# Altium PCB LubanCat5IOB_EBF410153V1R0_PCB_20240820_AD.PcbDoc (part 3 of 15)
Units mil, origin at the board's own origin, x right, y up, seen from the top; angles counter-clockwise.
Board outline 6811.02 x 4055.12 mil, 6 copper layers (TOP, GND02, ART03, ART04, PWR05, BOTTOM), stack 59.279 mil thick; 981 components, 783 nets, 3627 pads, 2669 vias.
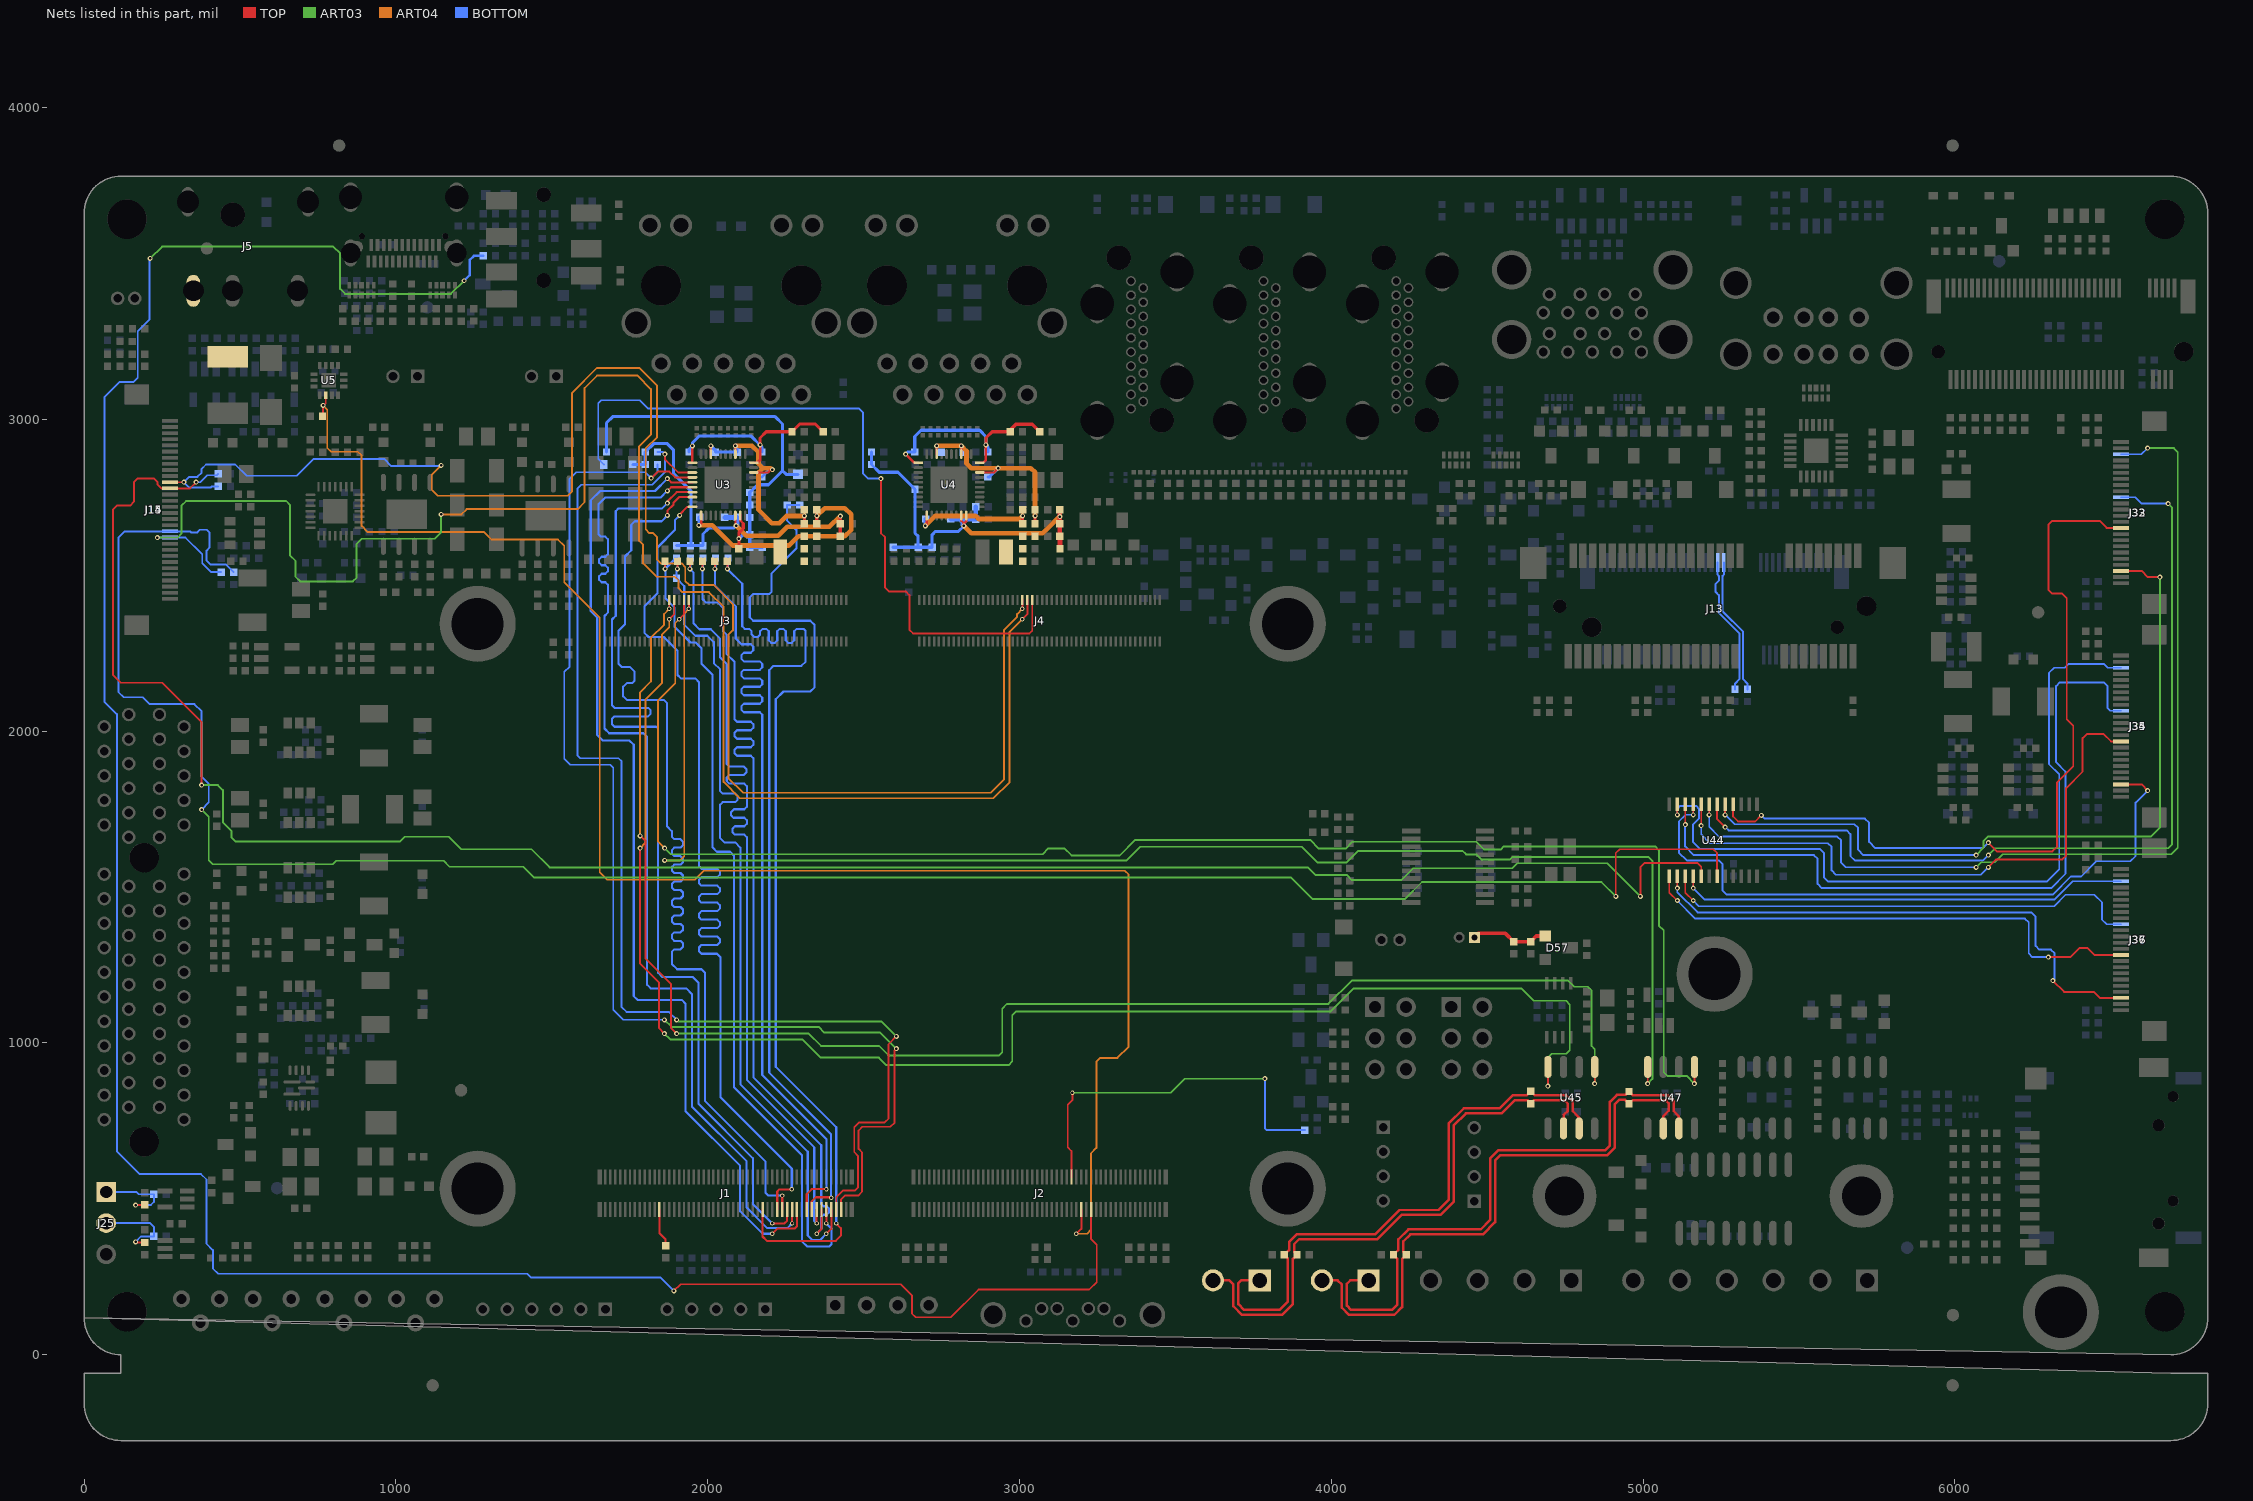
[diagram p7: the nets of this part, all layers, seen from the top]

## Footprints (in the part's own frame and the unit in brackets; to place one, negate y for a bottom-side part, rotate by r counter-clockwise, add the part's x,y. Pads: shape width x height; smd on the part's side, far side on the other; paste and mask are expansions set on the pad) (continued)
MARK#15 [mil] "MARK"
  round 40 smd far side: 1(-5748,-41) 1(-5323.89,-370.95) 1(-5023.89,3605.43) 1(-4933,2659) 1(-149.09,-370.95) 1(-149.09,3605.43) 1(-148,3380) 1(125,1126)
  round 40 smd: 1(-5523,2973) 1(-5041,148) 1(-295,3164) 1(0,0)
  body extent -5563,-411 40,3645, height 150
MARK#16 [mil] "MARK"
  round 40 smd far side: 1(-5453,-3205) 1(-5028.89,-3534.95) 1(-4728.89,441.43) 1(-4638,-505) 1(145.91,-3534.95) 1(145.91,441.43) 1(147,216) 1(420,-2038)
  round 40 smd: 1(-5228,-191) 1(-4746,-3016) 1(0,0) 1(295,-3164)
  body extent -5268,-3575 335,481, height 150
MIC2-4R00-TM [mm] "MIC2-4R00-TM"
  round 1.1 / inner round 1.524 / far side round 1.1 hole 0.7: 1(-0.7,-0.55) 2(0.7,-0.55)
  silkscreen extent -2,-2 2,2, body extent -2.11,-2.11 2.11,2.11, height 3.81
MSOP-8 [mm] "MSOP-8"
  rect 0.3x1 smd: 1(-0.975,-2.2) 2(-0.325,-2.2) 3(0.325,-2.2) 4(0.975,-2.2) 5(0.975,2.2) 6(0.325,2.2) 7(-0.325,2.2) 8(-0.975,2.2)
  silkscreen extent -1.5,-3.3 1.5,1.5, body extent -1.5,-2.8 1.5,2.8, height 3.81
NANO_SIM [mm] "NANO_SIM"
  rect 0.5x1.3 smd: 1(0.25,6.94) 2(-2.29,6.94) 3(-4.83,6.94) 4(2.47,6.94) 5(1.52,6.94) 6(-1.02,6.94) 7(-3.56,6.94)
  rect 1x2.1 smd: 8(-6.5,5.46) 9(6.5,5.46) 10(-6.5,-6.54) 11(6.5,-6.54)
  round 0.9 hole 0.9 unplated: ""(-5,-5.29) ""(3.5,-5.29)
  silkscreen extent -6.14,-7.6 6.14,5.9, body extent -7.05,-7.64 7.05,7.64, height 3.81
NPTH_M3 [mm] "NPTH_M3"
  round 3.2 / inner round 1.524 / far side round 3.2 hole 3.2 unplated: 1(0,0)
  body extent -3.11,-3.11 3.11,3.11, height 3.81
PCIE_52P [mm] "PCIE_52P"
  rect 0.6x2 smd: 1(-11.8,-4.1) 2(-11.4,4.1) 3(-11,-4.1) 4(-10.6,4.1) 5(-10.2,-4.1) 6(-9.8,4.1) 7(-9.4,-4.1) 8(-9,4.1) 9(-8.6,-4.1) 10(-8.2,4.1) 11(-7.8,-4.1) 12(-7.4,4.1) 13(-7,-4.1) 14(-6.6,4.1) 15(-6.2,-4.1) 16(-5.8,4.1) 17(-2.2,-4.1) 18(-1.8,4.1) 19(-1.4,-4.1) 20(-1,4.1) 21(-0.6,-4.1) 22(-0.2,4.1) 23(0.2,-4.1) 24(0.6,4.1) 25(1,-4.1) 26(1.4,4.1) 27(1.8,-4.1) 28(2.2,4.1) 29(2.6,-4.1) 30(3,4.1) 31(3.4,-4.1) 32(3.8,4.1) 33(4.2,-4.1) 34(4.6,4.1) 35(5,-4.1) 36(5.4,4.1) 37(5.8,-4.1) 38(6.2,4.1) 39(6.6,-4.1) 40(7,4.1) 41(7.4,-4.1) 42(7.8,4.1) 43(8.2,-4.1) 44(8.6,4.1) 45(9,-4.1) 46(9.4,4.1) 47(9.8,-4.1) 48(10.2,4.1) 49(10.6,-4.1) 50(11,4.1) 51(11.4,-4.1) 52(11.8,4.1)
  rect 2.15x2.6 smd: 53(14.65,-3.5) 54(-14.65,-3.5)
  round 1.6 hole 1.6 unplated: ""(-12.5,0)
  round 1.1 hole 1.1 unplated: ""(12.5,0)
  silkscreen extent -13.7,-4.6 13.7,49.64, body extent -15.8,-5.2 15.8,5.2, height 3.81
PCIE_64PIN_1R00 [mm] "PCIE_64PIN_1R00"
  round 1.1 hole 0.7: A1(-16.765,1.25) A4(-13.765,3.25) A12(-3.765,3.25) A15(-0.765,1.25) A18(2.235,3.25) A20(4.235,3.25) A23(7.235,1.25) A24(8.235,3.25) A27(11.235,1.25) A28(12.235,3.25) A31(15.235,1.25) B4(-13.765,-3.25) B7(-10.765,-1.25) B13(-2.765,-1.25) B16(0.235,-3.25) B18(2.235,-3.25) B21(5.235,-1.25) B22(6.235,-3.25) B25(9.235,-1.25) B26(10.235,-3.25) B29(13.235,-1.25) B32(16.235,-3.25)
  round 1.1 / inner round 1.524 / far side round 1.1 hole 0.7: A2(-15.765,3.25) A3(-14.765,1.25) A5(-12.765,1.25) A6(-11.765,3.25) A7(-10.765,1.25) A8(-9.765,3.25) A9(-8.765,1.25) A10(-7.765,3.25) A11(-6.765,1.25) A13(-2.765,1.25) A14(-1.765,3.25) A16(0.235,3.25) A17(1.235,1.25) A19(3.235,1.25) A21(5.235,1.25) A22(6.235,3.25) A25(9.235,1.25) A26(10.235,3.25) A29(13.235,1.25) A30(14.235,3.25) A32(16.235,3.25) B1(-16.765,-1.25) B2(-15.765,-3.25) B3(-14.765,-1.25) B5(-12.765,-1.25) B6(-11.765,-3.25) B8(-9.765,-3.25) B9(-8.765,-1.25) B10(-7.765,-3.25) B11(-6.765,-1.25) B12(-3.765,-3.25) B14(-1.765,-3.25) B15(-0.765,-1.25) B17(1.235,-1.25) B19(3.235,-1.25) B20(4.235,-3.25) B23(7.235,-1.25) B24(8.235,-3.25) B27(11.235,-1.25) B28(12.235,-3.25) B30(14.235,-3.25) B31(15.235,-1.25)
  round 2.4 hole 2.4 unplated: ""(-5.115,0) ""(18.035,0)
  silkscreen extent -19.61,-4.39 19.61,4.39, body extent -19.61,-4.39 19.61,4.39, height 3.81
PH-1X2-2P0_L [mm] "PH-1X2-2P0_L"
  rect 1.1x1.1 / inner round 1.524 / far side rect 1.1x1.1 hole 0.7: 1(-1,-0.6)
  round 1.1 / inner round 1.524 / far side round 1.1 hole 0.7: 2(1,-0.6)
  silkscreen extent -3,-2.6 3,2.6, body extent -3.1,-2.7 3.1,2.7, height 3.81
PH-1X4-2P0 [mm] "PH-1X4-2P0"
  rect 1.1x1.1 / inner round 1.524 / far side rect 1.1x1.1 hole 0.7: 1(-3,-0.6)
  round 1.1 / inner round 1.524 / far side round 1.1 hole 0.7: 2(-1,-0.6) 3(1,-0.6)
  round 1.1 hole 0.7: 4(3,-0.6)
  silkscreen extent -5,-2.6 5,2.6, body extent -5.1,-2.7 5.1,2.7, height 3.81
PH-1X5-2P0 [mm] "PH-1X5-2P0"
  rect 1.1x1.1 / inner round 1.524 / far side rect 1.1x1.1 hole 0.7: 1(-4,-0.6)
  round 1.1 / inner round 1.524 / far side round 1.1 hole 0.7: 2(-2,-0.6) 3(0,-0.6) 4(2,-0.6)
  round 1.1 hole 0.7: 5(4,-0.6)
  silkscreen extent -6,-2.6 6,2.6, body extent -6.13,-2.73 6.13,2.73, height 3.81
PH-1X6-2P0 [mm] "PH-1X6-2P0"
  rect 1.1x1.1 / inner round 1.524 / far side rect 1.1x1.1 hole 0.7: 1(-5,-0.6)
  round 1.1 hole 0.7: 2(-3,-0.6) 4(1,-0.6) 6(5,-0.6)
  round 1.1 / inner round 1.524 / far side round 1.1 hole 0.7: 3(-1,-0.6) 5(3,-0.6)
  silkscreen extent -7,-2.6 7,2.6, body extent -7.1,-2.7 7.1,2.7, height 3.81
QFN12-2R00X3R00 [mm] "QFN12-2R00X3R00"
  oval 1.4x0.25 smd: 1(-0.6,0.5) 2(-0.6,-0.5) 7(0.6,0)
  oval 0.25x0.8 smd: 3(-0.75,-1.45) 4(-0.25,-1.45) 5(0.25,-1.45) 6(0.75,-1.45) 9(0.75,1.45) 10(0.25,1.45) 11(-0.25,1.45) 12(-0.75,1.45)
  oval 0.8x0.25 smd: 8(0.9,0.5)
  silkscreen extent -2.25,-2 1.5,2, body extent -1.5,-2 1.5,2, height 3.81
QFN24 [mm] "QFN24"
  rect 1x0.3 smd: 1(-2.1,1.25) 2(-2.1,0.75) 3(-2.1,0.25) 4(-2.1,-0.25) 5(-2.1,-0.75) 6(-2.1,-1.25) 13(2.1,-1.25) 14(2.1,-0.75) 15(2.1,-0.25) 16(2.1,0.25) 17(2.1,0.75) 18(2.1,1.25)
  rect 0.3x1 smd: 7(-1.25,-2.1) 8(-0.75,-2.1) 9(-0.25,-2.1) 10(0.25,-2.1) 11(0.75,-2.1) 12(1.25,-2.1) 19(1.25,2.1) 20(0.75,2.1) 21(0.25,2.1) 22(-0.25,2.1) 23(-0.75,2.1) 24(-1.25,2.1)
  rect 2x2 smd: 25(0,0)
  silkscreen extent -3.35,-2.1 2.1,2.1, body extent -2.7,-2.7 2.7,2.7, height 3.81
QFN28_0R45-4X4EP2R6X2R6 [mm] "QFN28_0R45-4X4EP2R6X2R6"
  oval 0.8x0.2 smd: 1(-2,1.35)
  rect 0.8x0.2 smd: 2(-2,0.9) 3(-2,0.45) 4(-2,0) 5(-2,-0.45) 6(-2,-0.9) 7(-2,-1.35) 15(2,-1.35) 16(2,-0.9) 17(2,-0.45) 18(2,0) 19(2,0.45) 20(2,0.9) 21(2,1.35)
  rect 0.2x0.8 smd: 8(-1.35,-2) 9(-0.9,-2) 10(-0.45,-2) 11(0,-2) 12(0.45,-2) 13(0.9,-2) 14(1.35,-2) 22(1.35,2) 23(0.9,2) 24(0.45,2) 25(0,2) 26(-0.45,2) 27(-0.9,2) 28(-1.35,2)
  rect 2x2 smd: 29(0,0)
  silkscreen extent -3.15,-2 2,2.03, body extent -2.5,-2.5 2.5,2.5, height 3.81
QFP_40P_R [mil] "QFP_40P_R"
  oval 31.5x8.66 smd: 1(-98.43,70.87) 2(-98.43,55.12) 3(-98.43,39.37) 4(-98.43,23.62) 5(-98.43,7.87) 6(-98.43,-7.87) 7(-98.43,-23.62) 8(-98.43,-39.37) 9(-98.43,-55.12) 10(-98.43,-70.87) 21(98.43,-70.87) 22(98.43,-55.12) 23(98.43,-39.37) 24(98.43,-23.62) 25(98.43,-7.87) 26(98.43,7.87) 27(98.43,23.62) 28(98.43,39.37) 29(98.43,55.12) 30(98.43,70.87)
  oval 8.66x31.5 smd: 11(-70.87,-98.43) 12(-55.12,-98.43) 13(-39.37,-98.43) 14(-23.62,-98.43) 15(-7.87,-98.43) 16(7.87,-98.43) 17(23.62,-98.43) 18(39.37,-98.43) 19(55.12,-98.43) 20(70.87,-98.43) 31(70.87,98.43) 32(55.12,98.43) 33(39.37,98.43) 34(23.62,98.43) 35(7.87,98.43) 36(-7.87,98.43) 37(-23.62,98.43) 38(-39.37,98.43) 39(-55.12,98.43) 40(-70.87,98.43)
  rect 118.11x118.11 smd: 41(0,0)
  silkscreen extent -124,-98 98,124, body extent -116,-116 116,116, height 150
R0201#1 [mm] "R0201"
  rect 0.35x0.35 smd: 1(-0.275,0) 2(0.275,0)
  silkscreen extent -0.51,-0.25 0.51,0.25
R0201#2 [mm] "R0201"
  rect 0.35x0.35 smd: 1(0.275,0) 2(-0.275,0)
  silkscreen extent -0.51,-0.25 0.51,0.25, body extent -0.47,-0.18 0.47,0.18, height 3.81
R0402#1 [mil] "R0402"
  rect 23.6x23.6 smd: 1(-19.68,0) 2(19.68,0)
  silkscreen extent -37,-17 37,17, body extent -37,-17 37,17, height 150
R0402#2 [mil] "R0402"
  rect 23.6x23.6 smd: 1(19.68,0) 2(-19.68,0)
  silkscreen extent -37,-17 37,17, body extent -37,-17 37,17, height 150
R0603#1 [mil] "R0603"
  rect 31.5x31.5 smd: 1(-31.5,0) 2(31.5,0)
  silkscreen extent -54,-24 55,24, body extent -47,-16 47,16, height 150
R0603#2 [mil] "R0603"
  rect 31.5x31.5 smd: 1(31.5,0) 2(-31.5,0)
  silkscreen extent -55,-24 54,24, body extent -47,-16 47,16, height 150
R0805#1 [mil] "R0805"
  rect 40x45 smd: 1(-40,0) 2(40,0)
  silkscreen extent -70,-35 70,35, body extent -60,-25 60,25, height 150
R0805#2 [mil] "R0805"
  rect 40x45 smd: 1(40,0) 2(-40,0)
  silkscreen extent -70,-35 70,35, body extent -60,-25 60,25, height 150
SMA_CA [mm] "SMA_CA"
  rect 2.1x1.8 smd: 1(-2.2,0) 2(2.2,0)
  silkscreen extent -2.2,-1.3 2.2,1.3, body extent -3.3,-1.4 3.3,1.4, height 3.81
SMD4-6R80X2R50 [mm] "SMD4-6R80X2R50"
  rect 0.8x1.2 smd: 1(1.905,-1) 2(0.635,-1) 3(-0.635,-1) 4(-1.905,-1)
  silkscreen extent -3.4,-2.24 3.4,1.71, body extent -3.6,-1.8 3.6,1.8, height 3.81
SMTSO-M2R5 [mm] "SMTSO-M2R5"
  round 6.2 / inner round 5.2 / far side round 5.2 hole 4.22: 1(0,0)
  body extent -3.21,-3.21 3.21,3.21, height 3.81
SMTSO-M3#1 [mm] "SMTSO-M3"
  round 6.2 / inner round 5.2 / far side round 5.2 hole 4.22: 1(0,0)
  body extent -3.21,-3.21 3.21,3.21, height 3.81
SMTSO-M3#2 [mm] "SMTSO-M3"
  round 5.2 / inner round 5.2 / far side round 6.2 hole 4.22: 1(0,0)
  body extent -3.21,-3.21 3.21,3.21, height 3.81
SOD523 [mm] "SOD523"
  rect 0.6x0.7 smd: 1(-0.71,0) 2(0.71,0)
  silkscreen extent -1.3,-0.5 0.6,0.5, body extent -1.1,-0.4 1.1,0.4, height 3.81
SOD-123#1 [mm] "SOD-123"
  rect 1.2x1.4 smd: 1(1.7,0) 2(-1.7,0)
  silkscreen extent -1.8,-0.9 1.8,0.9, body extent -2.4,-1 2.4,1, height 3.81
SOD-123#2 [mm] "SOD-123"
  rect 1.2x1.4 smd: 1(-1.7,0) 2(1.7,0)
  silkscreen extent -1.8,-0.9 1.8,0.9, body extent -2.4,-1 2.4,1, height 3.81
SOIC16 [mil] "SOIC16"
  oval 80x24 smd: 1(-109.8,174.8) 2(-109.8,125.2) 3(-109.8,74.8) 4(-109.8,25.2) 5(-109.8,-25.2) 6(-109.8,-74.8) 7(-109.8,-125.2) 8(-109.8,-174.8) 9(109.8,-174.8) 10(109.8,-125.2) 11(109.8,-74.8) 12(109.8,-25.2) 13(109.8,25.2) 14(109.8,74.8) 15(109.8,125.2) 16(109.8,174.8)
  silkscreen extent -179,-197 59,197, body extent -157,-205 157,205, height 150
SOP8 [mm] "SOP8"
  oval 0.6x1.8 smd: 1(-1.905,-2.5) 2(-0.635,-2.5) 3(0.635,-2.5) 4(1.905,-2.5) 5(1.905,2.5) 6(0.635,2.5) 7(-0.635,2.5) 8(-1.905,2.5)
  silkscreen extent -2.5,-4.15 2.5,1.4, body extent -2.5,-3.5 2.5,3.5, height 3.81
SOP-8-EP-2R5X3R4 [mm] "SOP-8-EP-2R5X3R4"
  oval 0.4x1.4 smd: 1(-1.905,-2.6) 2(-0.635,-2.6) 3(0.635,-2.6) 4(1.905,-2.6) 5(1.905,2.6) 6(0.635,2.6) 7(-0.635,2.6) 8(-1.905,2.6)
  rect 3.3x2.4 smd: 9(0,0)
  silkscreen extent -2.79,-3.18 2.5,2, body extent -2.5,-3 2.5,3, height 3.81
SOT23#1 [mil] "SOT23"
  rect 36x36 smd: 1(-37.5,-43.5) 2(37.5,-43.5)
  rect 36x50 smd: 3(0,36.5)
  silkscreen extent -55,-54 55,36, body extent -56,-62 56,62, height 150
SOT23#2 [mil] "SOT23"
  rect 36x36 smd: 1(37.5,43.5) 2(-37.5,43.5)
  rect 36x50 smd: 3(0,-36.5)
  silkscreen extent -55,-36 55,54, body extent -56,-62 56,62, height 150
SOT23-5#1 [mm] "SOT23-5"
  rect 0.599x1.199 smd: 1(-1.026,-1.25) 2(-0.076,-1.25) 3(0.874,-1.25) 4(0.874,1.25) 5(-1.026,1.25)
  silkscreen extent -1.91,-2.35 1.42,0.9, body extent -1.52,-1.9 1.52,1.9, height 3.81
SOT23-5#2 [mm] "SOT23-5"
  rect 0.599x1.199 smd: 1(0.95,1.25) 2(0,1.25) 3(-0.95,1.25) 4(-0.95,-1.25) 5(0.95,-1.25)
  silkscreen extent -1.5,-0.9 1.91,1.78, body extent -1.6,-1.9 1.6,1.9, height 3.81
SOT23-5#3 [mm] "SOT23-5"
  rect 0.599x1.199 smd: 1(-0.95,-1.25) 2(0,-1.25) 3(0.95,-1.25) 4(0.95,1.25) 5(-0.95,1.25)
  silkscreen extent -2.08,-1.85 1.5,0.9, body extent -1.6,-1.9 1.6,1.9, height 3.81
SOT23-5#4 [mm] "SOT23-5"
  rect 0.599x1.199 smd: 1(-0.963,-1.25) 2(-0.013,-1.25) 3(0.937,-1.25) 4(0.937,1.25) 5(-0.963,1.25)
  silkscreen extent -1.84,-2.35 1.49,0.9, body extent -1.59,-1.9 1.59,1.9, height 3.81
SOT23-5#5 [mm] "SOT23-5"
  rect 0.599x1.199 smd: 1(-0.887,-1.25) 2(0.063,-1.25) 3(1.013,-1.25) 4(1.013,1.25) 5(-0.887,1.25)
  silkscreen extent -1.89,-2.35 1.56,0.9, body extent -1.54,-1.9 1.54,1.9, height 3.81
SOT23_6 [mm] "SOT23_6"
  rect 0.7x0.9 smd: 1(-0.95,-1.2) 2(0,-1.2) 3(0.95,-1.2) 4(0.95,1.2) 5(0,1.2) 6(-0.95,1.2)
  silkscreen extent -2.19,-1.25 1.4,0.6, body extent -1.4,-1.2 1.4,1.2, height 3.81
SOT563 [mm] "SOT563"
  rect 0.3x0.45 smd: 1(0.5,0.675) 2(0,0.675) 3(-0.5,0.675) 4(-0.5,-0.675) 5(0,-0.675) 6(0.5,-0.675)
  silkscreen extent -0.9,-1.1 0.9,1.8, body extent -0.9,-1.1 0.9,1.1, height 3.81
SOT-353 [mil] "SOT-353"
  rect 16x47 smd: 1(-25.91,-35.43) 2(-0.31,-35.43) 3(25.28,-35.43) 4(25.28,35.43) 5(-25.91,35.43)
  silkscreen extent -55,-80 45,70, body extent -40,-65 40,65, height 150
SSATA_V [mm] "SSATA_V"
  round 1.1 hole 0.75: 1(-3.81,0.95) 4(0,0.95) 7(3.81,0.95)
  round 1.1 / inner round 1.524 / far side round 1.1 hole 0.75: 2(-2.54,-0.05) 3(-1.27,-0.05) 5(1.27,-0.05) 6(2.54,-0.05)
  round 2.1 hole 1.5: S1(6.48,0.45) S2(-6.48,0.45)
  silkscreen extent -8,-3.25 8,3.2, body extent -8.1,-3.25 8.1,3.25, height 3.81
SW_TH_3P_4R5X5R5 [mm] "SW_TH_3P_4R5X5R5"
  round 1.4 hole 0.8: 1(-1.55,1.8) 3(0,-0.15)
  round 1.4 / inner round 1.524 / far side round 1.4 hole 0.8: 2(1.55,1.8)
  silkscreen extent -2.25,-2.75 2.25,2.75
T3R2-5R2_TOPSMT [mil] "T3R2-5R2_TOPSMT"
  round 204.72 hole 125.98: 1(0,0)
TFCARD [mil] "TFCARD"
  rect 27.56x62.99 smd: 1(88.58,206.82) 2(45.27,206.82) 3(1.97,206.82) 4(-41.34,206.82) 5(-84.65,206.82) 6(-127.95,206.82) 7(-171.26,206.82) 8(-214.57,206.82) 9(-257.88,206.82)
  rect 47.24x70 smd: 10(-305.12,187.13)
  rect 60x95 smd: 11(-305.12,-190.82) 12(305.12,-190.82)
  rect 70x70 smd: 13(269.68,187.13)
  round 39.37 hole 39.37 unplated: ""(-194.88,-206.57) ""(120.08,-206.57)
  silkscreen extent -289,-365 281,179, body extent -335,-238 335,238, height 150
TSSOP20 [mm] "TSSOP20"
  rect 0.4x1.5 smd: 1(-2.925,-3) 2(-2.275,-3) 3(-1.625,-3) 4(-0.975,-3) 5(-0.325,-3) 6(0.325,-3) 7(0.975,-3) 8(1.625,-3) 9(2.275,-3) 10(2.925,-3) 11(2.925,3) 12(2.275,3) 13(1.625,3) 14(0.975,3) 15(0.325,3) 16(-0.325,3) 17(-0.975,3) 18(-1.625,3) 19(-2.275,3) 20(-2.925,3)
  silkscreen extent -3.31,-4.61 3.3,2.1, body extent -3.3,-3.8 3.3,3.8, height 3.81
TSSOP24-0R65-7R80X4R40 [mm] "TSSOP24-0R65-7R80X4R40"
  rect 1.1x0.3 smd: 1(-2.95,3.575) 2(-2.95,2.925) 3(-2.95,2.275) 4(-2.95,1.625) 5(-2.95,0.975) 6(-2.95,0.325) 7(-2.95,-0.325) 8(-2.95,-0.975) 9(-2.95,-1.625) 10(-2.95,-2.275) 11(-2.95,-2.925) 12(-2.95,-3.575) 13(2.95,-3.575) 14(2.95,-2.925) 15(2.95,-2.275) 16(2.95,-1.625) 17(2.95,-0.975) 18(2.95,-0.325) 19(2.95,0.325) 20(2.95,0.975) 21(2.95,1.625) 22(2.95,2.275) 23(2.95,2.925) 24(2.95,3.575)
  silkscreen extent -4.1,-3.9 2.2,3.9, body extent -3.6,-4.1 3.6,4.1, height 3.81
USB3D0-AF-18P [mm] "USB3D0-AF-18P"
  round 1.1 / inner round 1.524 / far side round 1.1 hole 0.7: 1(-3.5,2.899) 2(-1.001,2.899) 3(1.001,2.899) 5(4,4.401) 6(1.999,4.401) 8(-1.999,4.401) 9(-4.001,4.401) 10(-3.5,6.1) 11(-1.001,6.1) 12(1.001,6.1) 14(4,7.601) 15(1.999,7.601) 17(-1.999,7.601) 18(-4.001,7.601)
  round 1.1 hole 0.7: 4(3.5,2.899) 7(0,4.401) 13(3.5,6.1) 16(0,7.601)
  round 3.2 / inner round 1.524 / far side round 3.2 hole 2.4: 19(6.571,0.9) 20(6.571,6.58) 21(-6.571,6.58) 22(-6.571,0.9)
  silkscreen extent -8,-16.73 8,8.77, body extent -8.4,-8.8 8.4,8.8, height 3.81
USB-A-D [mm] "USB-A-D"
  round 1.6 / inner round 1.524 / far side round 1.6 hole 1: 1(3.45,-7.425) 2(0.95,-7.425) 3(-1.05,-7.425) 7(3.45,-4.425) 8(0.95,-4.425) 9(-1.05,-4.425)
  round 1.6 hole 1: 4(-3.55,-7.425) 10(-3.55,-4.425)
  round 2.6 / inner round 1.524 / far side round 2.6 hole 2: 5(-6.6,-7.425) 6(6.5,-7.425) 11(-6.6,-1.625) 12(6.5,-1.625)
  silkscreen extent -7.75,-8.42 7.65,14.98, body extent -7.75,-9.08 7.75,9.08, height 3.81
USB-C-SMD_TYC-324G [mm] "USB-C-SMD_TYC-324G"
  oval 1x2.2 / inner round 1.524 / far side oval 1x2.2 hole 1.6 slot 0.6 at 0 deg: 1(-4.32,2.99) 4(4.32,2.99)
  oval 1.2x2.4 / inner round 1.524 / far side oval 1.2x2.4 hole 1.9 slot 0.6 at 0 deg: 2(-4.32,-1.56) 3(4.32,-1.56)
  rect 0.3x1 smd: A1(-2.62,3.68) A2(-2.13,3.68) A3(-1.63,3.68) A4(-1.13,3.68) A5(-0.62,3.68) A6(-0.12,3.68) A7(0.38,3.68) A8(0.88,3.68) A9(1.37,3.68) A10(1.87,3.68) A11(2.37,3.68) A12(2.88,3.68) B1(2.63,2.34) B2(2.13,2.34) B3(1.63,2.34) B4(1.13,2.34) B5(0.62,2.34) B6(0.12,2.34) B7(-0.38,2.34) B8(-0.87,2.34) B9(-1.37,2.34) B10(-1.87,2.34) B11(-2.37,2.34) B12(-2.88,2.34)
  oval 1.5x1 hole 0.5 slot 1.2 at 0 deg: ""(-4.06,2.51) ""(4.06,2.51)
  round 0.5 hole 0.5 unplated: ""(-3.4,1.63) ""(3.4,1.63)
  silkscreen extent -6,-10.14 6,1.67, body extent -4.97,-4.24 4.97,4.24, height 3.81
USON_10 [mm] "USON_10"
  rect 0.3x0.55 smd: 1(-1,-0.4) 2(-0.5,-0.4) 4(0.5,-0.4) 5(1,-0.4) 6(1,0.4) 7(0.5,0.4) 9(-0.5,0.4) 10(-1,0.4)
  rect 0.4x0.55 smd: 3(0,-0.4) 8(0,0.4)
  silkscreen extent -1.95,-0.95 1.3,0.5
WQFN14-0R50-2R5X2R5EP1R45X1R45 [mm] "WQFN14-0R50-2R5X2R5EP1R45X1R45"
  rect 0.6x0.3 smd: 1(-1.21,0.5) 2(-1.21,0) 3(-1.21,-0.5) 8(1.21,-0.5) 9(1.21,0) 10(1.21,0.5)
  rect 0.3x0.6 smd: 4(-0.75,-1.21) 5(-0.25,-1.21) 6(0.25,-1.21) 7(0.75,-1.21) 11(0.75,1.21) 12(0.25,1.21) 13(-0.25,1.21) 14(-0.75,1.21)
  rect 1.2x1.2 smd: 15(0,0)
  silkscreen extent -2.25,-1.25 1.25,1.25, body extent -1.6,-1.6 1.6,1.6, height 3.81
XH2P54-4P [mm] "XH2P54-4P"
  rect 1.45x1.45 / inner round 1.524 / far side rect 1.45x1.45 hole 0.85: 1(-3.81,0.508)
  round 1.45 hole 0.85: 2(-1.27,0.508) 3(1.27,0.508)
  round 1.45 / inner round 1.524 / far side round 1.45 hole 0.85: 4(3.81,0.508)
  silkscreen extent -6.51,-3.03 6.51,3.05, body extent -6.48,-3.05 6.48,3.05, height 3.81
ZH1P5MM_TH_2P [mm] "ZH1P5MM_TH_2P"
  round 1.05 / inner round 1.524 / far side round 1.05 hole 0.65: 1(-0.75,0.65)
  round 1.05 hole 0.65: 2(0.75,0.65)
  silkscreen extent -2.25,-1.85 2.25,1.85

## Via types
v1: diameter 16, hole 8, TOP to BOTTOM, 2357 vias
v2: diameter 14, hole 8, TOP to BOTTOM, 308 vias
v3: diameter 20, hole 10, TOP to BOTTOM, 4 vias

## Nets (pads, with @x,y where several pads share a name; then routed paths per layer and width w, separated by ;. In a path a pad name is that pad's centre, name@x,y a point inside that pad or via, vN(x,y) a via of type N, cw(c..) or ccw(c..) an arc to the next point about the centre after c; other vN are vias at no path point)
1V05_AVDD_PHY0: C40.1 C41.1 C42.1 C43.1 R47.2 U4.3 U4.8 U4.38 | length 722.8
  TOP w8: U4.8@2734.63,2888.43 v1(2734.63,2915) ; U4.3@2813.37,2888.43 v1(2813.37,2915) ; U4.38@2872.43,2829.37 2917.74,2829.37 v1(2931.8,2843.43)
  TOP w10: R47.2@3050,2664.68 v1(3050,2690) C42.1@3050,2710.32
  ART04 w15: v1(2734.63,2915) v1(2813.37,2915) 2830,2898.37 2830,2858.43 2845,2843.43 v1(2931.8,2843.43) 3036.57,2843.43 3050,2830 v1(3050,2690)
  BOTTOM w10: C41.1@2898.68,2815 2903.37,2815 v1(2931.8,2843.43)
1V05_AVDD_PHY1: C62.1 C63.1 C64.1 C65.1 R76.2 U3.3 U3.8 U3.38 | length 808.7
  TOP w8: U3.8@2010.22,2888.43 v1(2010.22,2915) ; U3.3@2088.96,2888.43 v1(2088.96,2915) ; U3.38@2148.02,2829.37 2193.33,2829.37 2202.39,2838.43 v1(2207.39,2838.43)
  TOP w10: R76.2@2310,2664.68 v1(2310,2690) C65.1@2310,2710.32
  ART04 w15: v1(2088.96,2915) 2142,2915 2163,2894 2163,2857.43 2177,2843.43 ; v1(2207.39,2838.43) 2202.39,2843.43 2177,2843.43 ; v1(2310,2690) 2253,2690 2230.11,2667.11 2205.89,2667.11 2163,2710 2163,2829.43 2177,2843.43
  BOTTOM w10: v1(2010.22,2915) 2024.59,2900.63 C62.1@2024.59,2894.68 C63.1@2094.59,2894.68 2094.59,2909.37 v1(2088.96,2915) ; C64.1@2174.27,2815 2197.7,2838.43 v1(2207.39,2838.43)
1V05_DVDD_PHY0: C38.1 C39.1 R46.1 U4.21 | length 437.4
  TOP w8: v1(2698.13,2658) 2703.13,2663 U4.21@2703.13,2691.57
  TOP w10: R46.1@3010,2664.68 v1(3010,2690) C39.1@3010,2710.32
  ART04 w15: v1(2698.13,2658) 2730.13,2690 2860,2690 2870,2680 3000,2680 v1(3010,2690)
  BOTTOM w15: v1(2698.13,2658) 2699,2658.87 C38.1@2699,2680.32
1V05_DVDD_PHY1: C60.1 C61.1 R75.1 U3.21 | length 821.2
  TOP w8: v1(1971.72,2660) 1978.72,2667 U3.21@1978.72,2691.57
  TOP w10: R75.1@2350,2664.68 v1(2350,2690) C60.1@2350,2710.32
  ART04 w15: v1(1971.72,2660) 2015,2660 2080,2595 2260,2595 2290,2625 2440,2625 2460,2645 2460,2695 2440,2715 2375,2715 v1(2350,2690)
  BOTTOM w15: v1(1971.72,2660) 1974.59,2662.87 C61.1@1974.59,2685.32
1V05_PHY0: C31.1 C32.1 L4.2 R46.2 R47.1
1V05_PHY1: C52.1 C53.1 L7.2 R75.2 R76.1
1V8_DVDD_PHY1: C50.1 C51.1 C59.1 R48.1 R49.1 R50.1 R61.1 R62.1 R70.1 R381.1 U3.28 | length 1300.9
  TOP w7: U3.28@2088.96,2691.57 2088.96,2661 v1(2090.96,2659)
  TOP w10: R381.1@2425.32,2625 C59.1@2425.32,2665 v1(2425.32,2689.68)
  ART04 w15: v1(2090.96,2659) 2123.96,2626 2226,2626 2255,2655 2390.64,2655 v1(2425.32,2689.68)
  BOTTOM w10: R70.1@1760,2855.32 1760.32,2855 R62.1@1799.91,2855 R61.1@1799.91,2895 1826.91,2922 1870.85,2922 1890,2902.85 1890,2827 1946.14,2770.86 1946.14,2595.82 R49.1@1945,2594.68 ; R50.1@1900,2594.68 R49.1@1945,2594.68 ; v1(2090.96,2659) 2082.96,2651 2004,2651 1985,2632 R48.1@1985,2594.68 R49.1@1945,2594.68
  BOTTOM w15: C50.1@2054.59,2685.32 C51.1@2094.59,2685.32 2094.59,2662.63 v1(2090.96,2659)
3V3_AVDD_PHY0: C44.1 C45.1 C46.1 R364.1 U4.11 U4.40 | length 730.7
  TOP w8: v1(2634.63,2888.42) 2662.18,2860.87 U4.11@2675.57,2860.87 ; U4.40@2872.43,2860.87 2884.43,2860.87 2892.43,2868.87 v1(2892.43,2917.8)
  TOP w10: v1(2892.43,2917.8) 2892.43,2940 2912.43,2960 C45.1@2970.32,2960
  TOP w12: C45.1@2970.32,2960 2970.32,2965.32 2989,2984 3041.32,2984 R364.1@3065.32,2960
  BOTTOM w10: v1(2634.63,2888.42) 2641.21,2895 C46.1@2664.32,2895 2664.32,2945 2684.32,2965 2872.43,2965 2892.43,2945 v1(2892.43,2917.8) 2898.68,2911.55 C44.1@2898.68,2895
3V3_AVDD_PHY1: C66.1 C67.1 C68.1 R383.1 U3.11 U3.40 | length 677.2
  TOP w8: U3.11@1951.16,2860.87 v1(1951.16,2915) ; U3.40@2148.02,2860.87 2160.02,2860.87 2168.02,2868.87 v1(2168.02,2917.8)
  TOP w10: v1(2168.02,2917.8) 2168.02,2940 2188.02,2960 C67.1@2270.32,2960 2295.32,2985 2345,2985 2370,2960 R383.1@2370.32,2960
  BOTTOM w10: C66.1@1939.91,2895 1939.91,2903.75 v1(1951.16,2915) 1951.16,2925 1972.16,2946 2139.82,2946 v1(2168.02,2917.8) 2174.27,2911.55 C68.1@2174.27,2895
3V3_DVDD_PHY0: C29.1 C30.1 C47.1 C48.1 C49.1 R20.1 R21.1 R22.1 R33.1 R34.1 R35.1 R41.1 R45.2 R363.1 U4.28 U4.29 | length 1355.7
  TOP w8: U4.28@2813.37,2691.57 2813.37,2674.63 2822,2666 ; v1(2822,2658) 2822,2666 ; U4.29@2829.12,2691.57 2829.12,2673.12 2822,2666
  TOP w15: C48.1@3129.68,2710 v1(3129.68,2688) C49.1@3129.68,2665 C47.1@3129.68,2625 3130,2624.68 R363.1@3130,2584.68
  ART04 w15: v1(2822,2658) 2845,2635 3075,2635 3128,2688 v1(3129.68,2688)
  BOTTOM w10: R33.1@2525.32,2895 R34.1@2525.32,2855 2550.32,2830 2610.32,2830 R41.1@2665,2775.32 2665,2635 2675,2625 R21.1@2675,2589.68 ; R22.1@2595,2589.68 R21.1@2675,2589.68 ; v1(2822,2658) 2804,2640 2730,2640 2720,2630 R20.1@2720,2589.68 R21.1@2675,2589.68
  BOTTOM w15: C30.1@2780,2680.32 C29.1@2819,2680.32 ; v1(2822,2658) 2819,2661 C29.1@2819,2680.32 ; R45.2@2860.32,2720 R35.1@2860.32,2680 2819.32,2680 C29.1@2819,2680.32
3V3_DVDD_PHY1: C69.1 C70.1 C71.1 R63.1 R64.2 R69.1 R73.2 R74.2 R382.1 U3.29 | length 1387.3
  TOP w8: U3.29@2104.71,2691.57 2104.71,2675.29 2114,2666
  TOP w10: C69.1@2100,2584.68 v1(2100,2617) 2100,2636 2114,2650 2114,2666
  BOTTOM w10: R69.1@1675.32,2895 1675.32,2988.5 1695.32,3008.5 2216.5,3008.5 2240,2985 2240,2835 ; R73.2@2135.32,2765 2160.32,2790 2195,2790 2240,2835 ; R64.2@2290,2823.5 2251.5,2823.5 2240,2835
  BOTTOM w12: v1(2100,2617) 2113,2630 C70.1@2135.32,2630 ; R73.2@2135.32,2765 R74.2@2135.32,2725 R63.1@2135.32,2685 C70.1@2135.32,2630 ; R382.1@2175,2589.68 C71.1@2135,2589.68 2135,2629.68 C70.1@2135.32,2630
12V_DC: F1.1 J5.4
AUTO_PWRON_EN: J1.24 R362.2 | length 124.1
  TOP w7: J1.24@1845.37,465.62 1845.37,389.63 1865,370 R362.2@1865,349.68
BAT_RTC: C238.1 D57.1 D59.1 J26.1 | length 250.6
  TOP w12: J26.1@4459.65,1338.42 4472.49,1351.26 4558.42,1351.26 D59.1@4585,1324.68 C238.1@4640,1324.68 4657.82,1342.5 D57.1@4686.5,1342.5
CAM0_NRST: J32.22 U44.5 | length 2509.2
  TOP w6: v1(5263.39,1731.61) U44.5@5263.39,1766.14 ; J32.22@6533.11,2513.7 6598.94,2513.7 6618.62,2494.01 v1(6657.99,2494.01)
  ART03 w6: v1(6068.11,1602.52) 6092.33,1626.74 6092.33,1648.17 6105.58,1661.42 6629.05,1661.42 6657.99,1690.36 v1(6657.99,2494.01)
  BOTTOM w6: v1(5263.39,1731.61) 5293.63,1701.37 5678,1701.37 5690,1689.37 5690,1619.37 5706.85,1602.52 v1(6068.11,1602.52)
CAM0_PWDN: J32.15 U44.4 | length 2552.5
  TOP w6: U44.4@5288.98,1766.14 5288.98,1726.02 5305,1710 5359.53,1710 v1(5379.53,1730) ; v1(6107.48,1641.89) 6135,1614.37 6313,1614.37 6328,1629.37 6328,1835.37 6380,1887.37 6380,2017 6359,2038 6359,2426 6344,2441 6312,2441 6300,2453 6300,2662.37 6312,2674.37 6464.09,2674.37 6486.97,2651.49 J32.15@6533.11,2651.49
  BOTTOM w6: v1(5379.53,1730) 5390.16,1719.37 5711.4,1719.37 5725,1705.77 5725,1644.37 5744.88,1624.49 6090.08,1624.49 v1(6107.48,1641.89)
CAM1_NRST: J33.22 U44.7 | length 3162.1
  TOP w6: v1(5212.2,1731.61) U44.7@5212.2,1766.14
  ART03 w6: v1(6068.11,1563.15) 6084.18,1579.22 6127.85,1579.22 6153.77,1605.14 6694.77,1605.14 6715,1625.37 6715,2894.8 6702.4,2907.4 v1(6617.99,2907.4)
  BOTTOM w6: v1(5212.2,1731.61) 5212.2,1692.79 5243.63,1661.37 5623,1661.37 5635,1649.37 5635,1577.97 5649.82,1563.15 v1(6068.11,1563.15) ; J33.22@6533.11,2887.72 6598.31,2887.72 v1(6617.99,2907.4)
CAM1_PWDN: J33.15 U44.6 | length 2883
  TOP w6: U44.6@5237.8,1766.14 5237.8,1717.84 v1(5263.39,1692.24)
  ART03 w6: v1(6107.48,1602.52) 6129.33,1624.37 6684.4,1624.37 6697,1636.97 6697,2716.77 v1(6684.4,2729.37)
  BOTTOM w6: v1(5263.39,1692.24) 5274.26,1681.37 5653,1681.37 5665,1669.37 5665,1599.37 5680,1584.37 6089.33,1584.37 v1(6107.48,1602.52) ; J33.15@6533.11,2749.92 6578.62,2749.92 6598.54,2730 6683.77,2730 v1(6684.4,2729.37)
CAM2_NRST: J34.22 U44.9 | length 2130
  TOP w6: v1(5161.02,1731.61) U44.9@5161.02,1766.14 ; J34.22@6533.11,1828.98 6598.94,1828.98 v1(6618.62,1809.29)
  BOTTOM w6: v1(5161.02,1731.61) 5136.61,1731.61 5115,1710 5115,1610 5140,1585 5243,1585 5255,1573 5255,1488.37 5267,1476.37 6315,1476.37 6372.25,1533.62 6405.25,1533.62 6454,1582.37 6563,1582.37 6580,1599.37 6580,1770.67 v1(6618.62,1809.29)
CAM2_PWDN: J34.15 U44.8 | length 1928.3
  TOP w6: v1(5186.61,1696.61) U44.8@5186.61,1766.14 ; v1(6107.48,1563.15) 6132.7,1588.37 6345,1588.37 6357,1600.37 6357,1817.37 6410,1870.37 6410,1977.37 6423.04,1990.41 6477.21,1990.41 6500.85,1966.77 J34.15@6533.11,1966.77
  BOTTOM w6: v1(5186.61,1696.61) 5186.61,1668.39 5214.63,1640.37 5593,1640.37 5605,1628.37 5605,1552.97 5618.6,1539.37 6083.7,1539.37 v1(6107.48,1563.15)
CAM3_NRST: J35.22 U44.11 | length 2425.5
  TOP w6: v1(5109.84,1731.61) U44.11@5109.84,1766.14
  BOTTOM w6: v1(5109.84,1731.61) 5109.84,1749.84 5120,1760 5170,1760 5180,1750 5180,1720 5160,1700 5160,1645 5183.63,1621.37 5568,1621.37 5580,1609.37 5580,1530.97 5593.6,1517.37 6295,1517.37 6335,1557.37 6335,1861.37 6302,1894.37 6302,2186.37 6318.62,2202.99 6351.99,2202.99 6364,2215 6479,2215 6491.01,2202.99 J35.22@6533.11,2202.99
CAM3_PWDN: J35.15 U44.10 | length 2384.1
  TOP w6: v1(5135.43,1700) U44.10@5135.43,1766.14
  BOTTOM w6: v1(5135.43,1700) 5135,1699.57 5135,1630 5162.63,1602.37 5548,1602.37 5560,1590.37 5560,1509.97 5573.6,1496.37 6309,1496.37 6355,1542.37 6355,1870.3 6325,1900.3 6325,2144.37 6337,2156.37 6478,2156.37 6489.56,2144.82 6489.56,2074.82 6499.17,2065.2 J35.15@6533.11,2065.2
CAM4_NRST: J36.22 U44.14 | length 1728.3
  TOP w6: v1(5109.84,1496.02) U44.14@5109.84,1533.86 ; v1(6314.37,1199.37) 6350.37,1163.37 6446,1163.37 6465.12,1144.25 J36.22@6533.11,1144.25
  BOTTOM w6: v1(5109.84,1496.02) 5109.84,1483.79 5175.27,1418.37 6245.63,1418.37 6259,1405 6259,1311 6271,1299 6308,1299 6320,1287 6320,1205 v1(6314.37,1199.37)
CAM4_PWDN: J36.15 U44.13 | length 1665.9
  TOP w6: U44.13@5084.25,1533.86 5084.25,1482.24 v1(5109.84,1456.65) ; v1(6300,1275) 6370.63,1275 6400,1304.37 6425,1304.37 6447.32,1282.05 J36.15@6533.11,1282.05
  BOTTOM w6: v1(5109.84,1456.65) 5168.13,1398.37 6225,1398.37 6237,1386.37 6237,1287 6249,1275 v1(6300,1275)
CAM5_NRST: J37.22 U44.16 | length 1449.5
  TOP w6: v1(5161.02,1496.02) U44.16@5161.02,1533.86
  BOTTOM w6: v1(5161.02,1496.02) 5197.68,1459.37 6319.37,1459.37 6378.27,1518.27 J37.22@6533.11,1518.27
CAM5_PWDN: J37.15 U44.15 | length 1553.9
  TOP w6: U44.15@5135.43,1533.86 5135.43,1482.24 v1(5161.02,1456.65)
  BOTTOM w6: v1(5161.02,1456.65) 5179.31,1438.37 6318.37,1438.37 6355,1475 6447.37,1475 6472,1450.37 6472,1395.47 6487,1380.47 J37.15@6533.11,1380.47
CAN1_H: D74.2 J40.1 R333.1 U45.7 | length 1879.7
  TOP w8: J40.1@3770.63,238.19 3710.82,238.19 3702,229.37 3702,162 3720.63,143.37 3834,143.37 3860,169.37 3860,309.68 D74.2@3849.68,320 3865,335.32 3865,361 3890.37,386.37 4141.37,386.37 4219,464 4344,464 4376.63,496.63 4376.63,741.63 4425,790 4540,790 4582.37,832.37 4627.69,832.37 R333.1@4640,844.68 4652.51,832.17 4754.13,832.17 4774.8,811.5 4774.8,780.57 4795,760.37 U45.7@4795,725.95
CAN1_L: D75.2 J40.2 R333.2 U45.6 | length 1870.2
  TOP w8: J40.2@3620.63,238.19 3673.18,238.19 3686,225.37 3686,155.37 3714,127.37 3842.37,127.37 3877.23,162.23 3877.23,306.91 D75.2@3890.32,320 3881,329.32 3881,354 3897.37,370.37 4148,370.37 4225.63,448 4350.63,448 4392.63,490 4392.63,735 4431.63,774 4546.63,774 4589,816.37 4628.95,816.37 R333.2@4640,805.32 4650.85,816.17 4747.5,816.17 4758.8,804.87 4758.8,782.17 4745,768.37 U45.6@4745,725.95
CAN1_RX_M1: J3.30 U45.4 | length 5003.5
  TOP w6: v1(1783.26,1624.37) 1783.26,1253.74 1844,1193 1844,1046.97 v1(1861.23,1029.74) ; v2(1876.88,2359) 1892.62,2374.75 J3.30@1892.62,2420.74 ; v1(4695,861.22) U45.4@4695,922.79
  ART03 w6: v1(1861.23,1029.74) 1879.97,1011 2304,1011 2362,953 2549,953 2573,929 2965,929 2977,941 2977,1089 2989,1101 3998,1101 4072,1175 4610,1175 4650,1135 4753,1135 4765,1123 4765,977 4753,965 4707,965 4695,953 v1(4695,861.22)
  ART04 w6: v1(1783.26,1624.37) 1800.26,1641.37 1800.26,2101.26 1853,2154 1853,2309 1876.88,2332.88 v2(1876.88,2359)
CAN1_TX_M1: J3.28 U45.1 | length 4992.5
  TOP w6: v1(1783.26,1663.74) 1801,1646 1801,1270 1882,1189 1882,1048.34 v1(1900.6,1029.74) ; v2(1876.88,2392) J3.28@1876.88,2420.74 ; v1(4845,869.37) U45.1@4845,922.79
  ART03 w6: v1(1900.6,1029.74) 2324.26,1029.74 2364,990 2550,990 2580,960 2935,960 2945,970 2945,1110 2960,1125 3991,1125 4066,1200 4760,1200 4780,1180 4823,1180 4835,1168 4835,990 4845,980 v1(4845,869.37)
  ART04 w6: v1(1783.26,1663.74) 1783.26,2124.26 1818,2159 1818,2299 1860.38,2341.38 1860.38,2375.5 v2(1876.88,2392)
CAN2_H: D76.2 J45.1 R355.1 U47.7 | length 1923.8
  TOP w8: J45.1@4120,238.19 4060.82,238.19 4050,227.37 4050,157.07 4063.7,143.37 4195.31,143.37 4211.31,159.37 4211.31,308.38 D76.2@4199.68,320 4215,335.32 4215,369.63 4247.37,402 4479.63,402 4509.63,432 4509.63,629.63 4535,655 4877.49,655 4893.49,671 4893.49,810.4 4916.46,833.37 4944.32,833.37 R355.1@4955,844.05 4966.28,832.77 5078.38,832.77 5098.4,812.75 5098.4,780.97 5115,764.37 U47.7@5115,725.95
CAN2_L: D77.2 J45.2 R355.2 U47.6 | length 1916
  TOP w8: J45.2@3970,238.19 3970.18,238.37 4020.39,238.37 4034,224.76 4034,150.44 4057.07,127.37 4201.93,127.37 4227.31,152.74 4227.31,306.99 D77.2@4240.32,320 4231,329.32 4231,363 4254,386 4486.25,386 4525.63,425.37 4525.63,623 4541.63,639 4884.11,639 4909.49,664.37 4909.49,803.77 4923.09,817.37 4942.32,817.37 R355.2@4955,804.69 4967.08,816.77 5071.75,816.77 5082.4,806.12 5082.4,782.77 5065,765.37 U47.6@5065,725.95
CAN2_RX_M0: J3.36 U47.4 | length 4914.2
  TOP w6: v2(1939.87,2392) J3.36@1939.87,2420.74 ; v1(5015,869.37) U47.4@5015,922.79
  ART03 w6: v1(1862,1585) 3344,1585 3388,1629 3906,1629 3957,1578 4048,1578 4086,1616 4421,1616 4432.39,1604.61 4465.39,1604.61 4481.61,1588.39 4573.39,1588.39 4581,1596 5018,1596 5030,1584 5030,884.37 v1(5015,869.37)
  ART04 w6: v1(1862,1585) 1912,1585 1924.87,1597.87 1924.87,2377 v2(1939.87,2392)
CAN2_TX_M0: J3.34 U47.1 | length 5000.4
  TOP w6: v2(1908.37,2359) 1924.12,2374.75 J3.34@1924.12,2420.74
  TOP w6.8: v1(5165,869.37) U47.1@5165,922.79
  ART03 w6: v1(1862,1624.37) 1881.37,1605 3074,1605 3093,1624 3144,1624 3167,1601 3321,1601 3371,1651 3932,1651 3960,1623 4046,1623 4068,1645 4465,1645 4490,1620 4543.46,1620 4553.46,1630 5039,1630 5051,1618 5051,1376 5066.37,1360.63 5066.37,906 5078.37,894 5140.37,894 v1(5165,869.37)
  ART04 w6: v1(1862,1624.37) 1841,1645.37 1841,2099 1896,2154 1896,2346.63 v2(1908.37,2359)
CTP0_INT: J4.44 J14.11 R301.2 | length 5275.8
  TOP w6: J14.11@275.91,2798.17 v1(320,2798.17) ; v2(3009.46,2392) J4.44@3009.46,2420.74
  ART04 w6: v1(1145.23,2852.48) 1115,2822.25 1115,2773.74 1133.74,2755 1551,2755 1565,2769 1565,3085 1645,3165 1780,3165 1838,3107 1838,2943 1801.48,2906.48 1801.48,2646.62 1813.1,2635 1825.1,2635 1838,2622.1 1838,2550 1850,2538 1916.21,2538 1928.21,2526 1928.21,2481 1940.21,2469 2019,2469 2081,2407 2081,2323 2066.6,2308.6 2066.6,1849.4 2113.93,1802.08 2908.07,1802.08 2950.93,1844.92 2950.93,2325.16 2992.46,2366.7 2992.46,2375 v2(3009.46,2392)
  BOTTOM w6: R301.2@430.32,2785 409.61,2785 405.78,2781.17 337,2781.17 v1(320,2798.17) 337,2815.17 363.17,2815.17 377,2829 377,2841 391,2855 485,2855 521,2819 682,2819 736,2873 962,2873 985,2850 1142.75,2850 v1(1145.23,2852.48)
CTP0_RST: J14.12 R303.2 U44.17 | length 6756.3
  TOP w6: v1(359.37,2798.17) 339.68,2778.49 J14.12@275.91,2778.49 248,2778.49 236,2790.49 236,2798.37 224,2810.37 172,2810.37 160,2798.37 160,2735.37 148,2723.37 105,2723.37 93,2711.37 93,2179 117,2155 251,2155 377.01,2028.99 v1(377.01,1826.85) ; v1(4991.42,1469.77) 4991.42,1563.42 5005,1577 5174.61,1577 5186.61,1565 U44.17@5186.61,1533.86
  ART03 w6: v1(377.01,1826.85) 429.15,1826.85 445,1811 445,1707 473,1679 473,1658 485,1646 1014,1646 1029,1661 1170,1661 1210,1621 1435,1621 1493,1563 3925,1563 3949,1539 4049,1539 4066,1522 4225,1522 4263,1560 4580,1560 4596,1576 4885.19,1576 v1(4991.42,1469.77)
  BOTTOM w6: v1(359.37,2798.17) 373.17,2798.17 395.54,2820.54 425.86,2820.54 R303.2@430.32,2825
CTP1_INT: J4.46 J15.11 R302.2 | length 5828.1
  TOP w6: v2(3009.46,2359) 3025.21,2374.75 J4.46@3025.21,2420.74
  ART03 w6: v1(235,2620.8) 300,2620.8 312,2632.8 312,2723 327,2738 648,2738 660,2726 660,2564 678,2546 678,2495 693,2480 862,2480 874,2492 874,2601 890,2617 1125,2617 1145.23,2637.23 v1(1145.23,2695)
  ART04 w6: v1(1145.23,2695) 1210,2695 1227,2712 1583,2712 1605,2734 1605,3100 1645,3140 1775,3140 1818,3097 1818,2951 1780,2913 1780,2610 1793,2597 1793,2538 1836,2495 1895,2495 1907,2483 1907,2458 1919,2446 2004,2446 2050.85,2399.15 2050.85,1837.15 2103.39,1784.61 2916.61,1784.61 2968.39,1836.39 2968.39,2317.93 v2(3009.46,2359)
  BOTTOM w6: v1(235,2620.8) J15.11@275.91,2620.8 325.27,2620.8 379,2567.06 379,2538 407.32,2509.68 R302.2@440,2509.68
CTP1_RST: J15.12 R304.2 U44.19 | length 6962.6
  TOP w6: v1(4912.68,1469.77) 4912.68,1609 4924.68,1621 5225.8,1621 5237.8,1609 U44.19@5237.8,1533.86
  ART03 w6: v1(377.01,1748.11) 400,1725.12 400,1585 412,1573 798,1573 809,1584 1153,1584 1172,1565 1408,1565 1442,1531 3870,1531 3939,1462 4237,1462 4291.02,1516.02 4866.43,1516.02 v1(4912.68,1469.77)
  BOTTOM w6: v1(377.01,1748.11) 400,1771.1 400,1830.37 377,1853.37 377,2063.37 354,2086.37 210,2086.37 188,2108.37 127,2108.37 110,2125.37 110,2619.37 131.12,2640.49 J15.12@275.91,2640.49 340.09,2640.49 343.44,2637.14 363.14,2637.14 371.62,2645.62 393.38,2645.62 401.86,2637.14 401.86,2587.86 393,2579 393,2547 406.11,2533.89 455.79,2533.89 R304.2@480,2509.68
DGB_RX: D55.1 J25.2 R291.1 | length 285.3
  TOP w6: v1(165,361.89) 167.21,359.68 R291.1@195,359.68
  BOTTOM w6: J25.2@70.86,421.89 211.74,421.89 223.74,409.89 D55.1@223.74,379.37 182.48,379.37 v1(165,361.89)
DGB_TX: D56.1 J25.1 R290.1 | length 273.6
  TOP w6: v1(165,480) 165.32,480.32 R290.1@195,480.32
  BOTTOM w6: J25.1@70.86,521.89 167.48,521.89 175,514.37 D56.1@223.74,514.37 223.74,489.68 214.06,480 v1(165,480)
EARPHONE_CTL: J2.72 R326.2 | length 8117.5
  TOP w6: v1(1891.95,204.63) 1913.32,226 2619,226 2655,190 2655,132 2667,120 2780,120 2869,209 3224,209 3248,233 3248,352 3229.93,370.07 J2.72@3229.93,465.62
  ART03 w6: v1(212,3516) 250,3554 799,3554 821,3532 821,3418 837,3402 1176.43,3402 v1(1218.8,3444.37)
  BOTTOM w6: v1(212,3516) 210,3514 210,3321 172,3283 172,3132.96 162.04,3123 159.04,3120 114,3120 65,3071 65,2094.37 105,2054.37 105,653 178.63,579.37 375,579.37 392.6,561.77 392.6,355.77 413,335.37 413,276.37 430,259.37 1421.63,259.37 1434,247 1849.58,247 v1(1891.95,204.63)
  BOTTOM w8: v1(1218.8,3444.37) 1237,3462.57 1237,3511.37 1250,3524.37 R326.2@1280.32,3524.37
EKEY_PETN0: C252.2 J13.37 | length 450.2
  BOTTOM w6.5: J13.37@5239.25,2540.77 5239.25,2501.5 5243.35,2497.41 5243.35,2482.44 5233,2472.09 5233,2446.09 5243.35,2435.75 5243.35,2379.39 5309.25,2313.49 5309.25,2166.45 5295,2152.2 C252.2@5295,2134.05
EKEY_PETP0: C251.2 J13.35 | length 441.6
  BOTTOM w6.5: J13.35@5258.94,2540.77 5258.94,2501.5 5254.85,2497.41 5254.85,2384.15 5320.75,2318.25 5320.75,2166.45 5335,2152.2 C251.2@5335,2134.05
FAN_CTRL: J2.63 R133.1 | length 1206.6
  TOP w6: J2.63@3166.93,569.96 3166.93,653.07 3155,665 3155,801 3170,816 v2(3170,840)
  ART03 w6: v2(3170,840) 3485,840 3530,885 v1(3787,885)
  BOTTOM w6: v1(3787,885) 3787,726 3793,720 R133.1@3915.32,720
FUSB302_INT: J2.68 R87.2 U5.5 | length 5413.6
  TOP w6: R87.2@764.68,3010 766.26,3011.58 v1(766.26,3045) 769.16,3045 775.16,3051 U5.5@775.16,3077.36 ; v2(3182.68,387.89) 3198.43,403.63 J2.68@3198.43,465.62
  ART04 w6: v1(766.26,3045) 780,3031.26 780,2908 792,2896 878,2896 890,2884 890,2658 910,2638 1283,2638 1307,2614 1520,2614 1540,2594 1540,2477 1654,2363 1654,1547 1678,1523 1958,1523 1987,1552 3338,1552 3350,1540 3350,988 3314,952 3259,952 3247,940 3247,663 3229.18,645.18 3229.18,400.18 3216.89,387.89 v2(3182.68,387.89)
GMAC0_MCLKINOUT: J1.66 R67.1 R68.1 | length 3221.7
  TOP w6.8: J1.66@2176.08,465.62 2176.08,378.92 2190,365 2410.63,365 2427.3,381.67 2427.3,405.89 v2(2412.3,420.89)
  BOTTOM w6.8: R68.1@2295,2725.32 R67.1@2255,2725.32 2255,2675 2285,2645 2285,2586 2205,2506 2205,2446.8 2198.2,2440 2146,2440 2135,2429 2135,2365 2146,2354 2329.4,2354 2343,2340.4 2343,2140.6 2329.4,2127 2243,2127 2218.4,2102.4 2218.4,923.6 2412.3,729.7 v2(2412.3,420.89)
GMAC0_MDC: J1.96 R61.2 U3.13 | length 3938.4
  TOP w6: v1(1862.85,2888.42) 1862.85,2872.15 1905.63,2829.37 U3.13@1951.16,2829.37 ; J1.96@2412.3,465.62 2412.3,504.78 2433.53,526 2472,526 2482,536 2482,638 2470,650 2470,729 2486,745 2568,745 2580,757 2580,995.63 v1(2605,1020.63)
  ART03 w6: v1(1900.6,1074.11) 1906.71,1068 2557.63,1068 v1(2605,1020.63)
  BOTTOM w6: R61.2@1839.27,2895 1856.27,2895 v1(1862.85,2888.42) 1862.85,2830.53 1822.32,2790 1594,2790 1582,2778 1582,1922 1591,1913 1714,1913 1724,1903 1724,1115 1740,1099 1875.71,1099 v1(1900.6,1074.11)
GMAC0_MDIO: J1.98 R62.2 U3.14 | length 3965.2
  TOP w6: v1(1819,2811) 1840,2832 1877,2832 1895.38,2813.62 U3.14@1951.16,2813.62 ; J1.98@2428.05,465.62 2428.05,498.25 2440.05,510.25 2482.25,510.25 2495,523 2495,649 2484,660 2484,719 2496,731 2586,731 2599.47,744.47 2599.47,975.73 v1(2605,981.26)
  ART03 w6: v1(1861.23,1074.11) 1884.34,1051 2356,1051 2374,1033 2553.26,1033 v1(2605,981.26)
  BOTTOM w6: R62.2@1839.27,2855 1839.27,2831.27 v1(1819,2811) 1800,2830 1578,2830 1557,2809 1557,2207 1540,2190 1540,1911 1559,1892 1688,1892 1697,1883 1697,1106 1728.89,1074.11 v1(1861.23,1074.11)
GMAC0_RSTN: D7.1 J4.48 | length 2388.5
  TOP w6: v1(2555.89,2809.68) 2555.89,2634.11 2569,2621 2569,2460 2581,2448 2635,2448 2647,2436 2647,2325 2659,2313 3032,2313 3040.95,2321.95 J4.48@3040.95,2420.74
  BOTTOM w6: D7.1@1667.05,2855 1649,2873.05 1649,3051 1659,3061 1782,3061 1808,3035 2485,3035 2498,3022 2498,2826.68 2515,2809.68 v1(2555.89,2809.68)
GMAC0_RXCLK: J1.86 R56.1 R59.1 | length 2745.3
  TOP w6.8: v1(2063.21,2520) R56.1@2063.21,2544.69 ; J1.86@2333.56,465.62 2333.56,491.56 2347,505 2394,505 v2(2396,503)
  BOTTOM w6.8: R59.1@2065,2555.32 2065,2521.79 v1(2063.21,2520) 2110.8,2472.41 2110.8,2336.2 2119,2328 2133.13,2328 2141.09,2320.03 2141.09,2309.97 2149.06,2302 2160.33,2302 2168.29,2309.97 2168.29,2320.03 2176.26,2328 2188.06,2328 2196.03,2320.03 2196.03,2290.97 2203.99,2283 2215.26,2283 2223.23,2290.97 2223.23,2320.03 2231.19,2328 2242.46,2328 2250.43,2320.03 2250.43,2290.97 2258.39,2283 2269.66,2283 2277.63,2290.97 2277.63,2320.03 2285.59,2328 2307.2,2328 2314,2321.2 2314,2222.6 2300.4,2209 2211.2,2209 2197.6,2195.4 2197.6,904.4 2396,706 v2(2396,503)
GMAC0_RXD0: J1.90 R48.2 R51.1 | length 2727.4
  TOP w6.8: v1(1983.21,2520) R51.1@1983.21,2544.69 ; v2(2349.31,387.89) 2365.06,403.63 J1.90@2365.06,465.62
  BOTTOM w6.8: R48.2@1985,2555.32 1985,2521.79 v1(1983.21,2520) 1983.21,2423.79 1994,2413 2032,2413 2049.36,2395.64 2049.36,2320.64 2061,2309 2061,2247 2086,2222 2086,2037.84 2093.97,2029.88 2138.63,2029.88 2146.6,2021.91 2146.6,2010.64 2138.63,2002.68 2093.97,2002.68 2086,1994.71 2086,1983.44 2093.97,1975.48 2138.63,1975.48 2146.6,1967.51 2146.6,1956.24 2138.63,1948.28 2093.97,1948.28 2086,1940.31 2086,1929.04 2093.97,1921.08 2138.63,1921.08 2146.6,1913.11 2146.6,889.82 2364.31,672.1 2364.31,483.98 2372.28,476.01 2382.03,476.01 2390,468.04 2390,456.78 2382.03,448.81 2372.28,448.81 2364.31,440.84 2364.31,402.89 v2(2349.31,387.89)
GMAC0_RXD1: J1.88 R49.2 R52.1 | length 2686.5
  TOP w6.8: v1(1943.21,2520) R52.1@1943.21,2544.69 ; v2(2349.31,420.89) J1.88@2349.31,465.62
  BOTTOM w6.8: R49.2@1945,2555.32 1945,2521.79 v1(1943.21,2520) 1954.87,2508.34 1954.87,2345.13 1973.4,2326.6 2010,2326.6 2040,2296.6 2040,2236 2061,2215 2061,1894.36 2068.97,1886.39 2116.03,1886.39 2124,1878.43 2124,1867.16 2116.03,1859.19 2068.97,1859.19 2061,1851.23 2061,1839.43 2068.97,1831.46 2117.83,1831.46 2125.8,1823.49 2125.8,1757.29 2117.83,1749.33 2084.37,1749.33 2075.4,1740.36 2075.4,1729.09 2082.37,1722.12 2117.83,1722.12 2125.8,1714.16 2125.8,1702.89 2117.83,1694.92 2087.37,1694.92 2079.4,1686.96 2079.4,1675.69 2087.37,1667.72 2117.83,1667.72 2125.8,1659.76 2125.8,881.2 2342,665 2342,428.2 v2(2349.31,420.89)
GMAC0_RXD2: J1.94 R54.1 R58.1 | length 2632.6
  TOP w6.8: v1(1903.21,2520) R54.1@1903.21,2544.69 ; v2(2380.81,387.89) 2396.55,403.63 J1.94@2396.55,465.62
  BOTTOM w6.8: v1(1903.21,2520) 1900,2516.79 R58.1@1900,2489.68 1924.87,2464.81 1924.87,2341.52 1960.59,2305.8 1999.2,2305.8 2020,2285 2020,2218 2040,2198 2040,1807.26 2047.97,1799.29 2088.03,1799.29 2096,1791.33 2096,1780.06 2088.03,1772.09 2047.97,1772.09 2040,1764.12 2040,1656.6 2053.6,1643 2088,1643 2105,1626 2105,867 2321,651 2321,382 2335,368 2360.92,368 v2(2380.81,387.89)
GMAC0_RXD3: J1.92 R50.2 R55.1 | length 2672.2
  TOP w6.8: v1(1863.21,2520) R55.1@1863.21,2544.69 ; v2(2380.81,420.89) J1.92@2380.81,465.62
  BOTTOM w6.8: R50.2@1900,2555.32 1898.53,2555.32 v1(1863.21,2520) 1865,2518.21 1865,2425.09 1893.37,2396.72 1893.37,2335.63 1945,2284 1962,2284 1980,2266 1980,2216 2016,2180 2016,1626.6 2029.6,1613 2072.2,1613 2084.2,1601 2084.2,858.38 2301.99,640.6 2301.99,364.02 2319,347 2390.2,347 2397,353.8 2397,404.69 v2(2380.81,420.89)
GMAC0_RXDV_CRS: J1.84 R57.1 R60.1 | length 2754.7
  TOP w6.8: v1(2023.21,2520) R57.1@2023.21,2544.69 ; J1.84@2317.82,465.62 2317.82,514.82 2334,531 v2(2381,531)
  BOTTOM w6.8: R60.1@2025,2555.32 2025,2521.79 v1(2023.21,2520) 2023.21,2466.79 2090,2400 2090,2297 2108.42,2278.58 2138.03,2278.58 2146,2270.61 2146,2259.35 2138.03,2251.38 2115.97,2251.38 2108,2243.41 2108,2231.61 2115.97,2223.64 2167.03,2223.64 2175,2215.68 2175,2204.41 2167.03,2196.45 2115.97,2196.45 2108,2188.48 2108,2177.21 2115.97,2169.24 2167.03,2169.24 2175,2161.28 2175,2150.01 2167.03,2142.05 2115.97,2142.05 2108,2134.08 2108,2122.81 2115.97,2114.84 2167.03,2114.84 2175,2106.88 2175,2095.61 2167.03,2087.64 2115.97,2087.64 2108,2079.68 2108,2068.41 2115.97,2060.45 2167.03,2060.45 2175,2052.48 2175,897 2381,691 v2(2381,531)
GMAC0_TXCLK: J1.72 U3.20 | length 3226
  TOP w6.8: v1(1910.22,2691.57) 1910.22,2694.63 1934.72,2719.13 U3.20@1951.16,2719.13 ; J1.72@2223.33,465.62 2223.33,523.2 2230.13,530 v2(2269.72,530)
  BOTTOM w6.8: v1(1910.22,2691.57) 1894.82,2676.17 1894.82,2644.82 1839,2589 1839,2442 1797.97,2400.97 1797.97,2314.03 1810,2302 1859,2302 1903,2258 1903,2180 1914,2169 1960,2169 1972,2157 1972,1566.53 1979.97,1558.57 2031.03,1558.57 2039,1550.6 2039,1539.33 2031.03,1531.37 1979.97,1531.37 1972,1523.4 1972,1512.13 1979.97,1504.17 2031.03,1504.17 2039,1496.2 2039,1484.93 2031.03,1476.97 1979.97,1476.97 1972,1469 1972,1457.73 1979.97,1449.77 2031.03,1449.77 2039,1441.8 2039,1430.53 2031.03,1422.57 1979.97,1422.57 1972,1414.6 1972,1403.33 1979.97,1395.37 2031.03,1395.37 2039,1387.4 2039,1376.13 2031.03,1368.17 1979.97,1368.17 1972,1360.2 1972,1348.93 1979.97,1340.97 2031.03,1340.97 2039,1333 2039,1321.73 2031.03,1313.77 1979.97,1313.77 1972,1305.8 1972,1294 1980,1286 2030,1286 2041,1275 2041,826 2269.72,597.28 v2(2269.72,530)
GMAC0_TXD0: J1.74 U3.18 | length 3245.4
  TOP w6.8: v1(1870.85,2691.57) 1870.85,2706.26 1890.59,2726 1890.59,2732 1909.22,2750.63 U3.18@1951.16,2750.63 ; J1.74@2239.07,465.62 v2(2239.07,510.36)
  BOTTOM w6.8: v1(1870.85,2691.57) 1852.28,2673 1766.6,2673 1755,2661.4 1755,2580 1735,2560 1735,2343 1713.82,2321.82 1713.82,2216.18 1725,2205 1751.4,2205 1765,2191.4 1765,2160.8 1758.2,2154 1740.8,2154 1729,2142.2 1729,2111.8 1740.8,2100 1859,2100 1870,2089 1870,1694 1885,1679 1885,1661.44 1892.97,1653.47 1913.03,1653.47 1921,1645.51 1921,1634.24 1913.03,1626.27 1892.97,1626.27 1885,1618.31 1885,1607.04 1892.97,1599.07 1913.03,1599.07 1921,1591.11 1921,1579.84 1913.03,1571.87 1892.97,1571.87 1885,1563.91 1885,1552.64 1892.97,1544.67 1913.03,1544.67 1921,1536.71 1921,1525.44 1913.03,1517.47 1892.97,1517.47 1885,1509.51 1885,1498.24 1892.97,1490.27 1913.03,1490.27 1921,1482.31 1921,1471.04 1913.03,1463.07 1892.97,1463.07 1885,1455.11 1885,1443.84 1892.97,1435.87 1913.03,1435.87 1921,1427.91 1921,1416.64 1913.03,1408.67 1892.97,1408.67 1885,1400.71 1885,1389.44 1892.97,1381.47 1913.03,1381.47 1921,1373.51 1921,1362.24 1913.03,1354.27 1892.97,1354.27 1885,1346.31 1885,1335.04 1892.97,1327.07 1913.03,1327.07 1921,1319.11 1921,1307.84 1913.03,1299.87 1892.97,1299.87 1885,1291.91 1885,1253 1902,1236 1980,1236 1992,1224 1992,813 2185,620 2185,520 2194.64,510.36 v2(2239.07,510.36)
GMAC0_TXD1: J1.76 U3.17 | length 3228.4
  TOP w6.8: v1(1870.85,2730.94) 1870.85,2736.26 1900.97,2766.38 U3.17@1951.16,2766.38 ; v2(2207.58,420.89) 2245.89,420.89 2254.82,429.82 J1.76@2254.82,465.62
  BOTTOM w6.8: v1(1870.85,2730.94) 1854.08,2714.17 1714.17,2714.17 1705,2705 1705,2370 1693.02,2358.02 1693.02,2082.53 1700.98,2074.57 1809.03,2074.57 1817,2066.6 1817,2055.33 1809.03,2047.37 1700.98,2047.37 1693.02,2039.4 1693.02,2021.98 1701,2014 1834.2,2014 1841,2007.2 1841,1225 1855,1211 1953,1211 1970.6,1193.4 1970.6,804.4 2145,630 2145,483.46 v2(2207.58,420.89)
GMAC0_TXD2: J1.78 U3.16 | length 3223.2
  TOP w6.8: v1(1870.85,2770.31) 1882.67,2782.13 U3.16@1951.16,2782.13 ; v2(2270.57,420.89) J1.78@2270.57,465.62
  BOTTOM w6.8: v1(1870.85,2770.31) 1849.74,2749.2 1671.2,2749.2 1650,2728 1650,2631.6 1657.97,2623.63 1672.03,2623.63 1680,2615.67 1680,2567.05 1672.03,2559.08 1659.97,2559.08 1652,2551.12 1652,2539.85 1659.97,2531.88 1672.03,2531.88 1680,2523.92 1680,2512.65 1672.03,2504.68 1659.97,2504.68 1652,2496.72 1652,2485.45 1659.97,2477.48 1672.03,2477.48 1680,2469.52 1680,2380 1669,2369 1669,2008.4 1684.4,1993 1794,1993 1806,1981 1806,1186 1817,1175 1930.8,1175 1949.8,1156 1949.8,795.2 2125,620 2125,471.8 2190.91,405.89 2255.57,405.89 v2(2270.57,420.89)
GMAC0_TXD3: J1.80 U3.15 | length 3247.7
  TOP w6.8: v1(1870.85,2809.68) 1882.66,2797.87 U3.15@1951.16,2797.87 ; v2(2207.58,387.89) 2224.69,405 2280,405 2286.32,411.32 J1.80@2286.32,465.62
  BOTTOM w6.8: v1(1870.85,2809.68) 1831.17,2770 1655,2770 1625,2740 1625,2385 1646,2364 1646,1987.6 1663.6,1970 1749,1970 1763,1956 1763,1150 1775,1138 1917,1138 1929,1126 1929,781 2104.2,605.8 2104.2,459.8 2176.11,387.89 v2(2207.58,387.89)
